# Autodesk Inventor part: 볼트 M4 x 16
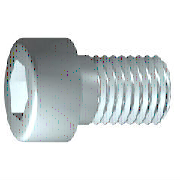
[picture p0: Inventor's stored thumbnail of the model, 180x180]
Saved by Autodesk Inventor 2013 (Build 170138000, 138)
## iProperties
Created: 2012-02
Part Number: 볼트 M4 x 16
Material: 스테인리스강
Description: 6각 소켓 머리 캡 나사
Document SubType Name: Modeling
Standard: ISO 4762
Designer: mduedu
Standard Revision: Fourth edition 2004-03-01
Standards Organization: ISO
Language: ko-KR
Size Designation: M4 x 16
Categories: <MemberInstance><Categories><Category DisplayName="조임쇠" InternalName="e4da775c-781d-43d5-af7c-5136215cf5a6" Mnemonic="FSTN"><Category DisplayName="볼트" InternalN
Density: 7.75 g/cm^3
IsCustomPart: 0
Author: mduedu
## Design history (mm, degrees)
sketch "스케치1"
  geometry: L1 (-1, 0)-(16, 0); L2 (16, 0)-(16, 2); L3 (16, 2)-(1.75, 2); L4 (1.75, 2)-(1.32, 2); L5 (1.32, 2)-(0, 2); L6 (0, 2)-(0, 3.5); L7 (0, 3.5)-(-4, 3.5); L8 (-4, 3.5)-(-4, 1.732); L9 (-4, 1.732)-(-2, 1.732); L10 (-2, 1.732)-(-1, 0); L11 (-8, 0)-(20, 0) reference; L12 (0, -0.7)-(0, 4.2) reference; L13 (1.75, 2)-(0, 2)
  constraints: 22 end point, 6 parallel, 2 collinear, 2 perpendicular, 1 horizontal, 1 point on line
  dimensions: "d1" = 14.25 distance from line of L3.end L2 (= GEL); "d2" = 0.42952 distance of L4.end L3.end (computed from GAL); "d3" = 4 distance between parallel lines of L8 L6 (= KOH); "d4" = 2 distance of L8.end L9.end (= INTI); "d5" = 60 deg angle of L10 L1; "d6" = 4 diameter of L3 L1 (= GD); "d7" = 4 diameter of L5 L1 (= BDM); "d8" = 3.4641 diameter of L9 L1 (= 1.1547 x SW); "d9" = 7 diameter of L7 L1 (= KOD); "d26" = 16 distance between parallel lines of L12 L2 (= NLG)
revolve "본체" sketch "스케치1" stored, may be unused: angle "d10" = 90 deg
sketch "스케치2"
  geometry: L1 (0, -4.9)-(0, 4.9) reference; L2 (-4.9, 0)-(4.9, 0) reference; L3 (1.732, 0)-(0.866, -1.5); L4 (0.866, -1.5)-(-0.866, -1.5); L5 (-0.866, -1.5)-(-1.732, 0); L6 (-1.732, 0)-(-0.866, 1.5); L7 (-0.866, 1.5)-(0.866, 1.5); L8 (0.866, 1.5)-(1.732, 0); 2 further points
  constraints: 12 end point, 1 coincident, 1 horizontal alignment, 1 point on line, 12 other
extrude "슬롯" join sketch "스케치2" stored distance "d11" = 10; taper "d12" = 0 deg
workplane "Work Plane1"
fillet "Fillet2" dims "d30" = 0.1 (= R)
body "Solid1"
fillet "모깎기1" dims "d17" = 0.4 (= RR)
feature "스레드" dims "d13" = 14.25 (= GEL), "d14" = 0
chamfer "모따기1" distance "d15" = 0.42941 (= -0.5 x SPD + 0.5 x GD); stored, may be unused: second distance "d16" = 0.42941 (= GUL), angle "d27" = 45 deg
other parameters: "GD" = 4 [user parameter; used in 2 equation terms], "NLG" = 16 [user parameter; used in 1 equation term], "GEL" = 14.25 [user parameter; used in 2 equation terms], "KOD" = 7 [user parameter; used in 1 equation term], "KOH" = 4 [user parameter; used in 1 equation term], "INTI" = 2 [user parameter; used in 1 equation term], "GAL" = 0.42941 (= 0.61345 x PTC) [user parameter; used in 1 equation term], "GUL" = 0.42941 (= 0.61345 x PTC) [user parameter; used in 1 equation term], "BDM" = 4 (= NND) [user parameter; used in 1 equation term], "SW" = 3 [user parameter; used in 2 equation terms], "RR" = 0.4 [user parameter; used in 1 equation term], "SPD" = 3.14117 (= NND - 1.2269 x PTC) [user parameter; used in 1 equation term], "d19" = 0, "d28" = 0, "d29" = 0, "R" = 0.1 [user parameter; used in 1 equation term], "TOA" = 30 deg [user parameter], "GD1" = 3.14117 (= THREADDIA - 1.2269 x PTC) [user parameter], "THREADDIA" = 4 [user parameter; used in 1 equation term], "FAWI" = 45 deg [user parameter], "TPU" = 14.28571 (computed from PTC) [user parameter], "PTC" = 0.7 [user parameter; used in 5 equation terms], "NND" = 4 [user parameter; used in 2 equation terms], "E0" = 3.465 (= 1.155 x SW) [user parameter]
